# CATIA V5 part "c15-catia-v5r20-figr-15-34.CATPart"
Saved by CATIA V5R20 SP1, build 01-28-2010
Part number: Part1
Bounding box of the stored display mesh (mm): x -40.264 to 42.014, y -25.445 to 25.445, z -51 to 0.75
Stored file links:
  D:\v5_r20\psrt_files_downloaded\c15\c15-catia-v5r20-figr-15-34.CATPart
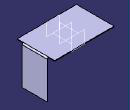
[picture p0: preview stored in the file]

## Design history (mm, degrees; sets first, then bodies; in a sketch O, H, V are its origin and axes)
SheetMetalParameters1: Thickness 0.75, BendRadius 1, KFactor 0.356492 {= log(min(100,max(20*SheetMetalParameters1.BendRadius,SheetMetalParameters1.Thickness)/SheetMetalParameters1.Thickness))/log(100)/2}, ReliefRadialLength 1, ReliefAxialLength 2, MinimumBendRadius 0
Body1 (main body)
  Sketch1 on xy-plane, origin (0, 0, 0), H (1, 0, 0), V (0, 1, 0)
    line L1 (-40.2643, 25.445) -> (40.2643, 25.445)
    line L2 (40.2643, 25.445) -> (40.2643, -25.445)
    line L3 (40.2643, -25.445) -> (-40.2643, -25.445)
    line L4 (-40.2643, -25.445) -> (-40.2643, 25.445)
    horizontal: L1 H, L3 H
    vertical: L2 V, L4 V
    symmetry: L1 L3 H, L4 L2 V
  Wall1: Thickness 0.75, Profile Sketch1
  Plane1: type Offset, RefPlane zx-plane, Offset 17
  Plane2: type Offset, RefPlane zx-plane, Offset 17, reversed
  Flange1: Angle 90, Length 50, Radius 1, KFacteur 0.356492 {= log(min(100,max(20*Flange1.Radius,SheetMetalParameters1.Thickness)/SheetMetalParameters1.Thickness))/log(100)/2}, Guide edge [face of Wall1 | face of Wall1], Limit1 Plane1, Limit2 Plane2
